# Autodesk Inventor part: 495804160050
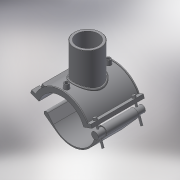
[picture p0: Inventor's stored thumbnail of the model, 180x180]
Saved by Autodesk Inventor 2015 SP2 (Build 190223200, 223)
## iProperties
Created: 2017-07
Part Number: 495804160050
Material: Generic
Description: PLASSON BRANCH SADDLE 160-50
Document SubType Name: Modeling
Designer: KIM
Density: 1 g/cm^3
Appearance: Default
Author: KIM
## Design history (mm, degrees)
derived "495804.ipt"
feature "Solid1::495804.ipt"
feature "Solid2::495804.ipt"
tag "TaggingFeature1"
body "Solid1"
body "Solid2"
other parameters: "H_" = 93, "L_" = 118, "d_t" = 6, "H_1" = 82, "d1" = 182, "d148" = 4, "d160" = 4, "d4" = 118, "d5" = 0, "d6" = 0.1, "d8" = 0, "d19" = 6, "d20" = 6, "d21" = 70.8, "d23" = 0, "d24" = 35.4, "d26" = 0, "d27" = 3, "d28" = 3, "d29" = 3, "d30" = 53.33333, "d31" = 6, "d32" = 0, "d33" = 0, "d34" = 0.6, "d40" = 94.64, "d41" = 55, "d43" = 0, "d45" = 0, "d47" = 184, "d50" = 0, "d70" = 15, "d72" = 0, "d73" = 6, "d75" = 5, "d76" = 0, "d77" = 8, "d79" = 15, "d80" = 47.2, "d82" = 5 deg, "d84" = 4, "d85" = 14, "d86" = 0, "d87" = 3, "d88" = 0, "d89" = 1, "d90" = 1, "d91" = 94.4, "d92" = 0, "d93" = 0.5, "d94" = 84.21053, "d96" = 185.64, "d97" = 2.36, "d98" = 0, "d102" = 1.5, "d105" = 0, "d109" = -31, "d117" = 0.5, "d120" = 140 deg, "d121" = 24.228, "d122" = 20 deg, "d123" = 364, "d124" = 109.2, "d126" = 0, "d143" = 168, "d150" = 28.8, "d159" = 4.4, "d161" = 4, "d162" = 70.8, "d163" = 0, "d167" = 32, "d168" = 82.72727, "d173" = 1, "d176" = 20 deg, "d177" = 11.2, "d178" = 22, "d180" = 0, "d185" = 38.35, "d186" = 38.35, "d187" = 91, "d188" = 6.6, "d189" = 11.2, "d190" = 0, "d191" = 136.5, "d200" = 11, "d202" = 0, "d216" = 106.2, "d217" = 0, "d221" = 43.66, "d222" = 11.2, "d223" = 6.72, "d225" = 6.72, "d227" = 23.04, "d230" = 99.2, "d236" = 20 deg, "d237" = 98, "d238" = 20 deg, "d239" = 11.2
